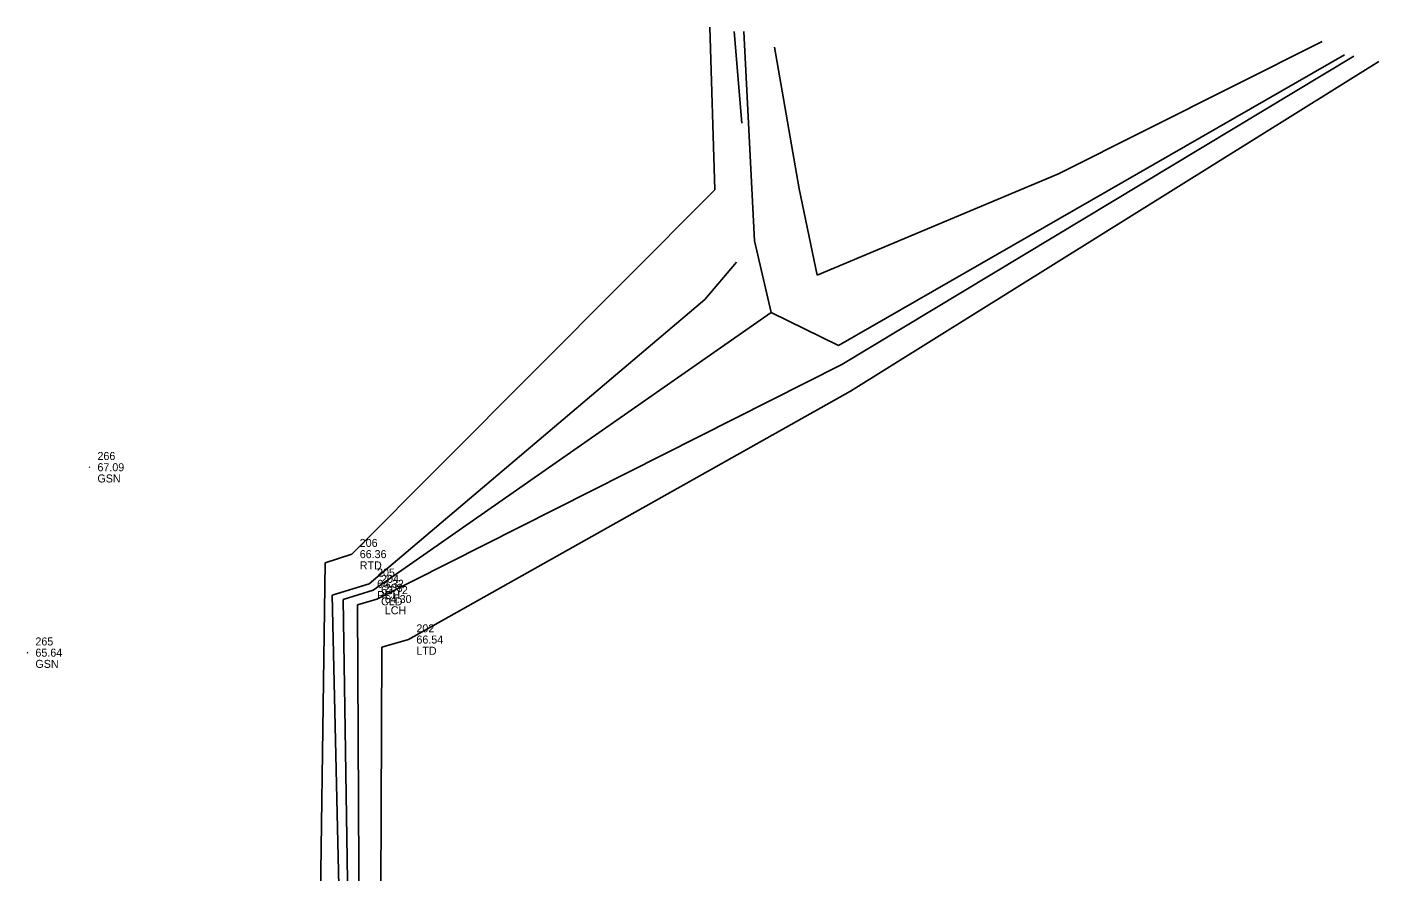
# Model space of a CAD drawing. Extents: x 2396723 to 2397333, y 558720 to 559221.
# Drawn here: x 2397062.9 to 2397333.1, y 559052.4 to 559221.4 of the extents above; entities that cross this region are included whole.
import ezdxf

# ---------------------------------------------------------------- set-up
doc = ezdxf.new("R2010")
doc.units = 0
doc.layers.add('Old_Level_1', color=7, linetype='Continuous')
doc.layers.add('Old_Level_2', color=7, linetype='Continuous')

# ---------------------------------------------------------------- blocks, each defined once
blk = doc.blocks.new('_U123')
at = {"layer": 'Old_Level_1'}
for p, q in [((0.05, 0.05), (-0.05, -0.05)), ((0.05, -0.05), (-0.05, 0.05))]:
    blk.add_line(p, q, dxfattribs=at)
for s, p in [('202', (1.22, 1.1)), ('66.54', (1.22, -0.61)), ('LTD', (1.22, -2.32))]:
    blk.add_text(s, height=1.219, dxfattribs=at).set_placement(p)
blk = doc.blocks.new('_U124')
at = {"layer": 'Old_Level_1'}
for p, q in [((0.05, 0.05), (-0.05, -0.05)), ((0.05, -0.05), (-0.05, 0.05))]:
    blk.add_line(p, q, dxfattribs=at)
for s, p in [('203', (1.22, 1.1)), ('64.30', (1.22, -0.61)), ('LCH', (1.22, -2.32))]:
    blk.add_text(s, height=1.219, dxfattribs=at).set_placement(p)
blk = doc.blocks.new('_U125')
at = {"layer": 'Old_Level_1'}
for p, q in [((0.05, 0.05), (-0.05, -0.05)), ((0.05, -0.05), (-0.05, 0.05))]:
    blk.add_line(p, q, dxfattribs=at)
for s, p in [('204', (1.22, 1.1)), ('63.72', (1.22, -0.61)), ('CLD', (1.22, -2.32))]:
    blk.add_text(s, height=1.219, dxfattribs=at).set_placement(p)
blk = doc.blocks.new('_U126')
at = {"layer": 'Old_Level_1'}
for p, q in [((0.05, 0.05), (-0.05, -0.05)), ((0.05, -0.05), (-0.05, 0.05))]:
    blk.add_line(p, q, dxfattribs=at)
for s, p in [('205', (1.22, 1.1)), ('64.32', (1.22, -0.61)), ('RCH', (1.22, -2.32))]:
    blk.add_text(s, height=1.219, dxfattribs=at).set_placement(p)
blk = doc.blocks.new('_U127')
at = {"layer": 'Old_Level_1'}
for p, q in [((0.05, 0.05), (-0.05, -0.05)), ((0.05, -0.05), (-0.05, 0.05))]:
    blk.add_line(p, q, dxfattribs=at)
for s, p in [('206', (1.22, 1.1)), ('66.36', (1.22, -0.61)), ('RTD', (1.22, -2.32))]:
    blk.add_text(s, height=1.219, dxfattribs=at).set_placement(p)
blk = doc.blocks.new('_U186')
at = {"layer": 'Old_Level_1'}
for p, q in [((0.05, 0.05), (-0.05, -0.05)), ((0.05, -0.05), (-0.05, 0.05))]:
    blk.add_line(p, q, dxfattribs=at)
for s, p in [('265', (1.22, 1.1)), ('65.64', (1.22, -0.61)), ('GSN', (1.22, -2.32))]:
    blk.add_text(s, height=1.219, dxfattribs=at).set_placement(p)
blk = doc.blocks.new('_U187')
at = {"layer": 'Old_Level_1'}
for p, q in [((0.05, 0.05), (-0.05, -0.05)), ((0.05, -0.05), (-0.05, 0.05))]:
    blk.add_line(p, q, dxfattribs=at)
for s, p in [('266', (1.22, 1.1)), ('67.09', (1.22, -0.61)), ('GSN', (1.22, -2.32))]:
    blk.add_text(s, height=1.219, dxfattribs=at).set_placement(p)

msp = doc.modelspace()

# ---------------------------------------------------------------- linework, layer by layer
at = {"layer": 'Old_Level_1'}
for p, q in [((2397200.34, 559188.82), (2397199.36, 559221.4)), ((2397205.8, 559202.17), (2397204.26, 559220.47)), ((2397208.3, 559178.65), (2397206.14, 559220.52)), ((2397321.78, 559218.52), (2397269.09, 559192.06)), ((2397217.23, 559189.02), (2397212.3, 559217.35)), ((2397225.11, 559157.73), (2397326.21, 559215.81)), ((2397328.12, 559215.6), (2397225.73, 559153.91)), ((2397333.12, 559214.5), (2397227.46, 559148.6)), ((2397269.09, 559192.06), (2397220.83, 559171.77)), ((2397127.79, 559115.99), (2397200.34, 559188.82)), ((2397220.83, 559171.77), (2397217.23, 559189.02)), ((2397211.63, 559164.29), (2397208.3, 559178.65)), ((2397198.38, 559166.88), (2397204.69, 559174.39)), ((2397131.25, 559110.06), (2397198.38, 559166.88)), ((2397132.05, 559108.79), (2397211.63, 559164.29)), ((2397211.63, 559164.29), (2397225.11, 559157.73)), ((2397225.73, 559153.91), (2397132.8, 559107.01)), ((2397227.46, 559148.6), (2397139.12, 559098.91)), ((2397122.45, 559114.25), (2397127.79, 559115.99)), ((2397123.91, 559107.82), (2397131.25, 559110.06)), ((2397126.05, 559106.93), (2397132.05, 559108.79)), ((2397132.8, 559107.01), (2397128.95, 559105.83)), ((2397139.12, 559098.91), (2397133.82, 559097.37))]:
    msp.add_line(p, q, dxfattribs=at)
for points in [[(2397145.98, 558846.14), (2397119.95, 558933.75), (2397122.45, 559114.25)], [(2397150.05, 558846.8), (2397127.91, 558933.33), (2397123.91, 559107.82)], [(2397150.5, 558847.42), (2397128.71, 558933.75), (2397126.05, 559106.93)], [(2397128.95, 559105.83), (2397129.81, 558934.44), (2397151.5, 558847.54)], [(2397133.82, 559097.37), (2397133.12, 558935.13), (2397155.22, 558849.51)]]:
    msp.add_lwpolyline(points, dxfattribs=at)

# ---------------------------------------------------------------- block references
at = {"layer": 'Old_Level_1', "xscale": 1.3123333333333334, "yscale": 1.3123333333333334}
for name, p in [('_U187', (2397075.36, 559133.37)), ('_U127', (2397127.79, 559115.99)), ('_U125', (2397132.05, 559108.79))]:
    msp.add_blockref(name, p, dxfattribs=at)
at = {"layer": 'Old_Level_2', "xscale": 1.3123333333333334, "yscale": 1.3123333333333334}
for name, p in [('_U187', (2397075.36, 559133.37)), ('_U127', (2397127.79, 559115.99)), ('_U126', (2397131.25, 559110.06)), ('_U126', (2397131.25, 559110.06)), ('_U125', (2397132.05, 559108.79)), ('_U124', (2397132.8, 559107.01)), ('_U124', (2397132.8, 559107.01)), ('_U123', (2397139.12, 559098.91)), ('_U123', (2397139.12, 559098.91)), ('_U186', (2397062.96, 559096.29)), ('_U186', (2397062.96, 559096.29))]:
    msp.add_blockref(name, p, dxfattribs=at)

doc.saveas('drawing.dxf')
